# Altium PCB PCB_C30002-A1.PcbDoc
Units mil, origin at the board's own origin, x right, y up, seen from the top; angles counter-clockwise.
Board outline 2417.95 x 1905 mil, 2 copper layers (Top, Bottom), stack 10 mil thick; 53 components, 38 nets, 141 pads, 18 vias.
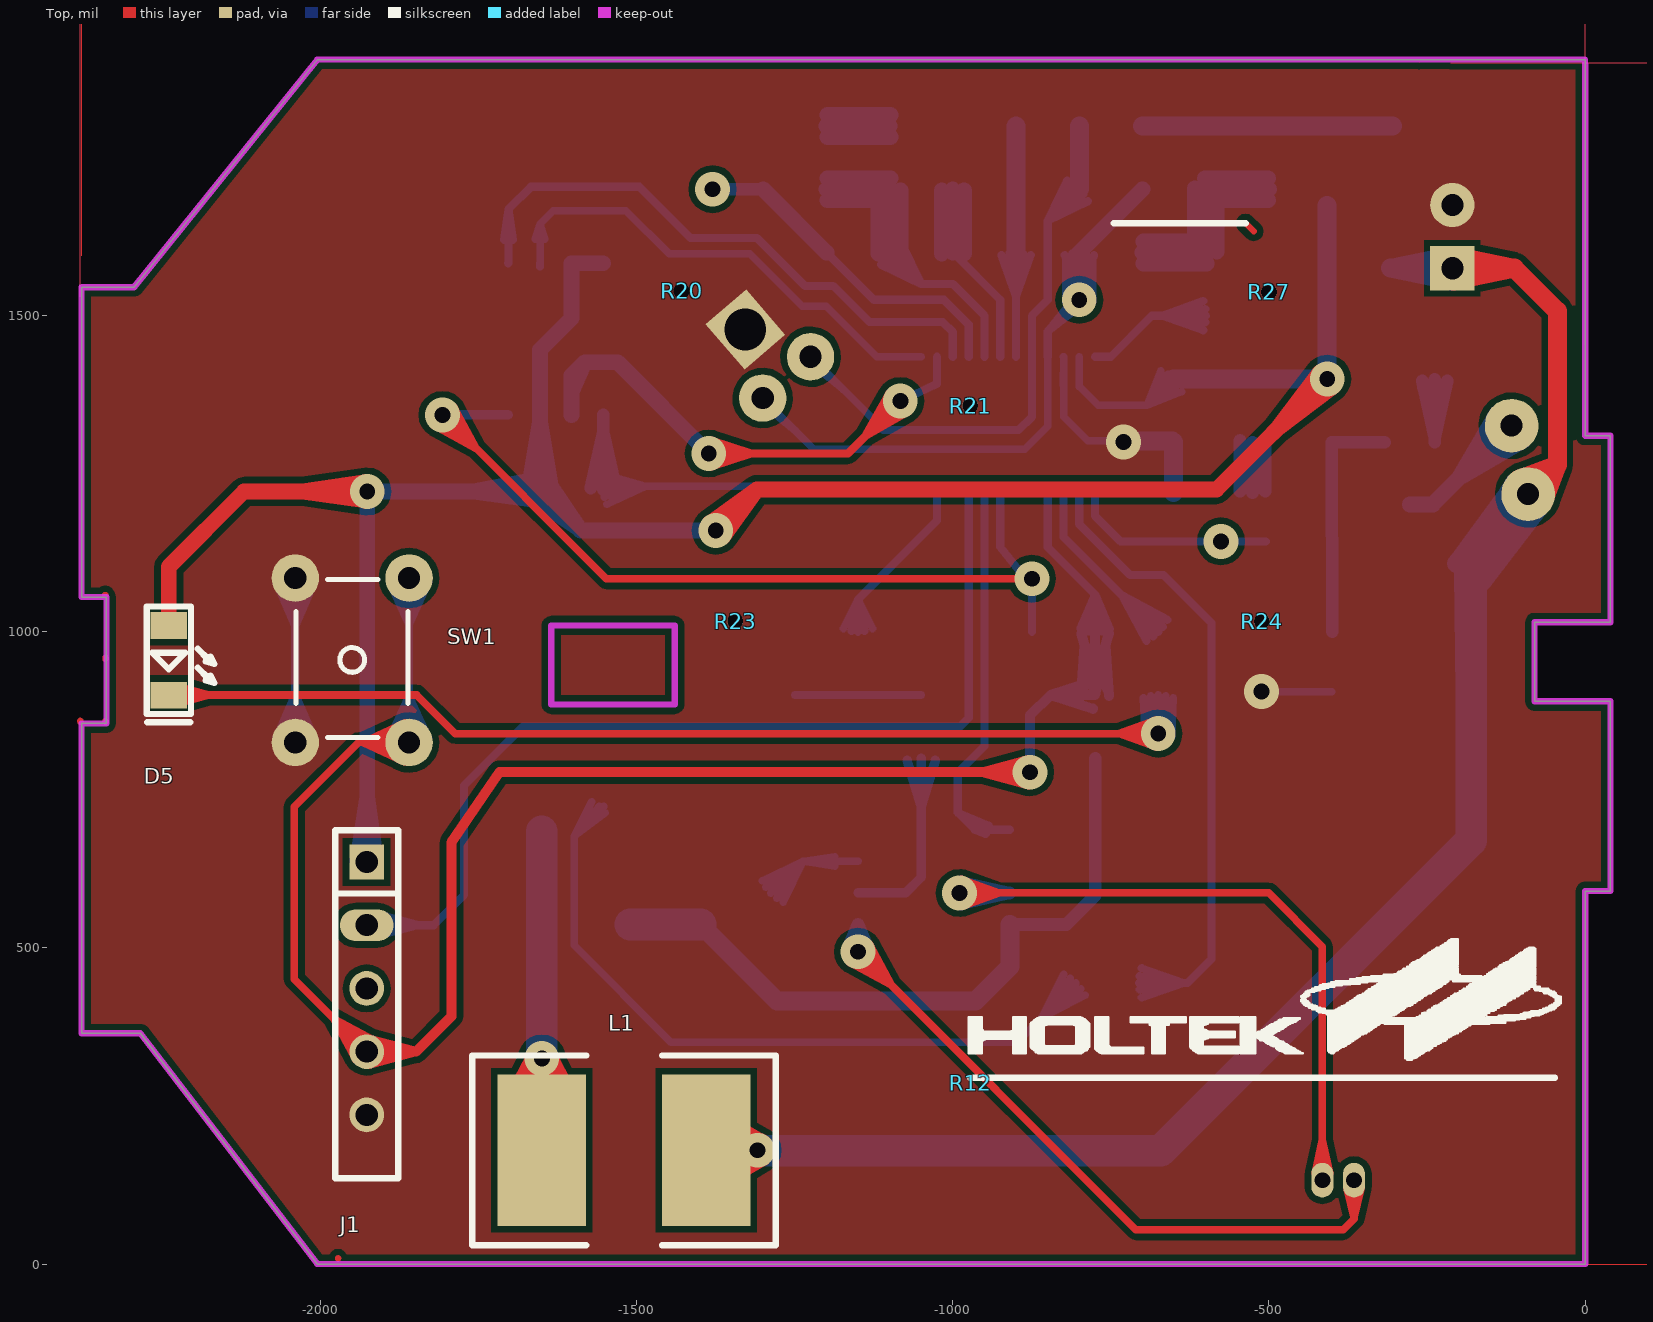
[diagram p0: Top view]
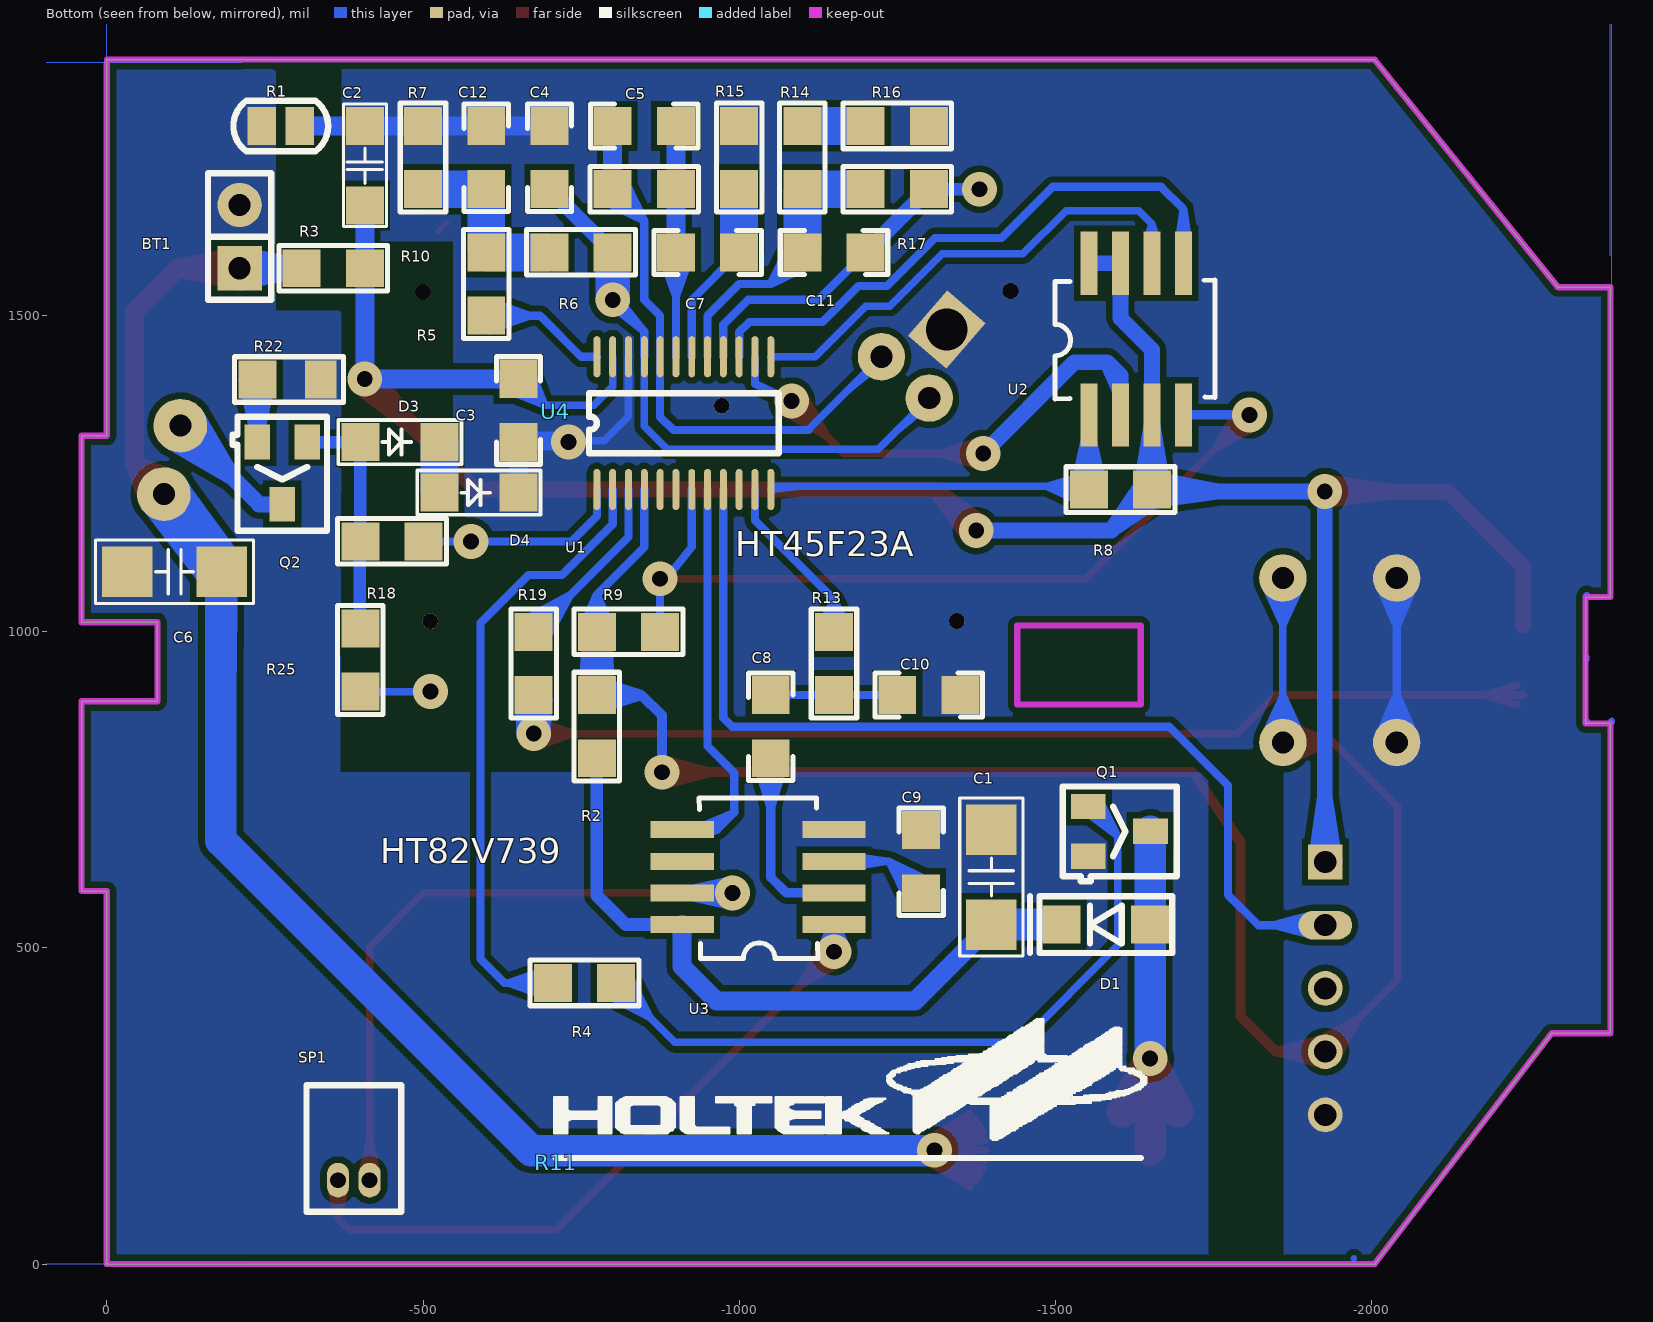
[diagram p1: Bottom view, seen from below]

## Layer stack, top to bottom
Top: signal copper 1
Dielectric: dielectric 8, FR-4, Dk 3.8
Bottom: signal copper 1

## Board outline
0,590 0,0 -2005,0 -2285,365 -2377.95,365 -2377.95,855 -2338.58,855 -2338.58,1055 -2377.95,1055 -2377.95,1545 -2295,1545 -2005,1905 -0.08,1905 0,1895 0,1310 40,1310 40,1015 -80,1015 -80,890 40,890 40,590

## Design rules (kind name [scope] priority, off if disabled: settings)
Clearance [All] p1: gap=10
MinimumSolderMaskSliver [All] p1: minsoldermaskwidth=6
PlaneConnect "Power Plane Connect Style - pads with no thermal" [(Name='J1-3') Or (Name='R20-1') Or (Name='R21-1') Or (Name='R23-1') Or (Name='R24-1') Or (Name='R27-1')] p1: planeconnectstyle=NoConnect reliefexpansion=20 reliefentries=4 reliefconductorwidth=10 reliefairgap=10 // PAD - No Thermal Connect Rule
PlaneConnect [All] p2: planeconnectstyle=Relief reliefexpansion=20 reliefentries=4 reliefconductorwidth=10 reliefairgap=10
PolygonConnect [All] p1: connectstyle=Direct reliefconductorwidth=10 reliefentries=4 polygonreliefangle="90 Angle" airgapwidth=10
RoutingVias [All] p1: holewidth=28 width=50 viastyle="Through Hole" minholewidth=28 minwidth=50 maxholewidth=28 maxwidth=50
SilkToSilkClearance [All] p1: silktosilkclearance=6
SilkscreenOverComponentPads [All] p1: minsilkscreentomaskgap=1
SolderMaskExpansion [All] p1: expansion=4
Width [All] p1: maxlimit=60 minlimit=10 preferedwidth=10
24 further rules are at their usual default settings.

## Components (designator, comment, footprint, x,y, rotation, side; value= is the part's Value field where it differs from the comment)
BT1 "BATAAA" BATAAA -210,1575 r90 bottom
C1 "CAP1206AAA" CAP1206AAA -1399,537 r90 bottom
C2 "CAP1206" CAP1206 -408,1737 r90 bottom
C3 "CAP0805" CAP0805 -651,1300 r90 bottom
C4 "CAP0805" CAP0805 -700,1800 r270 bottom
C5 "CAP0805" CAP0805 -900,1800 r0 bottom
C6 "CAP1206AAA" CAP1206AAA -32,1095 r180 bottom
C7 "CAP0805" CAP0805 -1000,1600 r0 bottom
C8 "CAP0805" CAP0805 -1050,900 r270 bottom
C9 "CAP0805" CAP0805 -1287.8,586.5 r90 bottom
C10 "CAP0805" CAP0805 -1350,900 r0 bottom
C11 "CAP0805" CAP0805 -1200,1600 r0 bottom
C12 "CAP0805" CAP0805 -600,1800 r270 bottom
D1 "DIO1206A" DIO1206A -1650,537 r0 bottom
D3 "DIO0805AA" DIO0805AA -401,1300 r180 bottom
D4 "DIO0805AA" DIO0805AA -526,1220 r180 bottom
D5 "LED\0805_BIN" LED\0805_BIN -2240,955 r270 top
J1 "CON5AAAAA" CON5AAAAA -1927,336 r270 top
L1 "IND-1810AAA" IND-1810AAA -1390,180 r180 top
Q1 "SOT-23S_HOLTEK" SOT-23S_HOLTEK -1552,645 r0 bottom
Q2 "SOT-23S_HOLTEK" SOT-23S_HOLTEK -238,1300 r90 bottom
R1 "JUMPER_SMD-01" JUMPER_SMD-01 -275,1800 r0 bottom
R2 "RES0805" RES0805#1 -775,800 r90 bottom
R3 "RES0805" RES0805#1 -308,1575 r180 bottom
R4 "RES0805" RES0805#1 -705.4,444.6 r180 bottom
R5 "RES0805" RES0805#1 -600,1500 r90 bottom
R6 "RES0805" RES0805#1 -700,1600 r180 bottom
R7 "RES0805" RES0805#1 -500,1800 r270 bottom
R8 "RES0805" RES0805#1 -1653,1225 r0 bottom
R9 "RES0805" RES0805#1 -775,1000 r180 bottom
R10 "RES0805" RES0805#1 -900,1700 r0 bottom
R11 "HOLTEK_LOGO匕AA" HOLTEK_LOGO匕AA -709.7,160 r180 bottom
R12 "HOLTEK_LOGO匕AA" HOLTEK_LOGO匕AA -972.8,286.6 r0 top
R13 "RES0805" RES0805#1 -1150,1000 r270 bottom
R14 "RES0805" RES0805#1 -1100,1800 r270 bottom
R15 "RES0805" RES0805#1 -1000,1800 r270 bottom
R16 "RES0805" RES0805#1 -1200,1800 r180 bottom
R17 "RES0805" RES0805#1 -1200,1700 r180 bottom
R18 "RES0805" RES0805#1 -501,1143 r0 bottom
R19 "RES0805" RES0805#1 -675,1000 r270 bottom
R20 "PUNCHB" PUNCHB -1429,1539.1 r0 top
R21 "PUNCHB" PUNCHB -972.4,1357.5 r0 top
R22 "RES0805" RES0805#2 -338,1399 r0 bottom
R23 "PUNCHAA" PUNCHAA -1344.1,1017 r0 top
R24 "PUNCHB" PUNCHB -511.5,1016.6 r0 top
R25 "RES0805" RES0805#1 -400.8,1005.4 r270 bottom
R27 "PUNCHB" PUNCHB -500,1537.5 r0 top
SP1 "SP1AAA" SP1AAA -415.6,132.7 r0 bottom
SW1 "SW-TS06" SW-TS06 -1950,955 r0 top
U1 "SSOP24A" SSOP24A -775,1225 r90 bottom locked
U2 "SOP8-150" SOP8-150 -1553,1343 r90 bottom
U3 "SOP8-150" SOP8-150 -1150,537 r0 bottom
U4 "SMOKE-5AAAAAAAAAAAAAAAAAA" SMOKE-5AAAAAAAAAAAAAAAAAA -1225,1435 r310.8 bottom locked

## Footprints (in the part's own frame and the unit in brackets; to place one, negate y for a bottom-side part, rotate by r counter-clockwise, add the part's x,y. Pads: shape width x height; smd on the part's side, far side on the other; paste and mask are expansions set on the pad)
BATAAA [mil]
  rect 70x70 / inner round 55 / far side rect 70x70 hole 35: 1(0,0)
  round 70 / inner round 55 / far side round 70 hole 35: 2(100,0)
  silkscreen extent -50,-50 150,50
CAP0805 [mil]
  rect 60x60 smd: 1(0,0) 2(100,0)
  silkscreen extent -35,-35 135,35
CAP1206 [mil]
  rect 60x60 smd: 1(-63,0) 2(63,0)
  silkscreen extent -96,-34 98,34
CAP1206AAA [mil]
  rect 80x80 smd: 1(0,0) 2(150,0)
  silkscreen extent -50,-50 200,50
CON5AAAAA [mil]
  rect 55x55 / inner round 55 / far side rect 55x55 hole 35: 1(-300,0)
  oval 50x85 / inner oval 45x85 / far side oval 45x85 hole 35: 2(-200,0)
  round 55 hole 35: 3(-100,0) 4(0,0) 5(100,0)
  silkscreen extent -350,-50 200,50
DIO0805AA [mil]
  rect 60x60 smd: N(125,0) P(0,0)
  silkscreen extent -35,-35 160,35
DIO1206A [mil]
  rect 60x60 smd: N(140,0) P(0,0)
  silkscreen extent -35,-45 190,45
HOLTEK_LOGO匕AA [mil]
  silkscreen extent -2,8 934,227
IND-1810AAA [mil]
  rect 140x240 smd: 1(0,0) 2(260,0)
  silkscreen extent -110,-150 370,150
JUMPER_SMD-01 [mil]
  rect 45x60 smd: 1(-30,0) 2(30,0)
  silkscreen extent -75,-40 75,40
LED\0805_BIN [mil]
  rect 42x58 smd: A(-55,0) K(55,0)
  silkscreen extent -85,-35 98,72
PUNCHAA [mil]
  round 25 hole 25: 1(0,0)
PUNCHB [mil]
  round 25 hole 25: 1(0,0)
RES0805#1 [mil]
  rect 60x60 smd: 1(0,0) 2(100,0)
  silkscreen extent -36,-36 136,36
RES0805#2 [mil]
  rect 50x60 smd: 1(0,0)
  rect 60x60 smd: 2(100,0)
  silkscreen extent -36,-36 136,36
SMOKE-5AAAAAAAAAAAAAAAAAA [mil]
  round 85 hole 35: 1(906,-717) 2(807,-768)
  round 75 hole 35: 3(0,0) 4(0,100)
  rect 95x80 / inner rect 95x85 / far side rect 95x85 hole 66: 5(-100,50)
SOP8-150 [mil]
  rect 100x27 smd: 1(0,0) 2(0,-50) 3(0,-100) 4(0,-150) 5(240,-150) 6(240,-100) 7(240,-50) 8(240,0)
  silkscreen extent 25,-200 213,54
SOT-23S_HOLTEK [mil]
  rect 55x40 smd: B(0,-78.74) C(-98.43,-39.37) E(0,0)
  silkscreen extent -140,-110 40,39
SP1AAA [mil]
  oval 35x55 hole 25: 1(0,0) 2(50,0)
  silkscreen extent -50,-150 100,50
SSOP24A [mil]
  oval 65x11 smd: 1(0,0) 2(0,-25) 3(0,-50) 4(0,-75) 5(0,-100) 6(0,-125) 7(0,-150) 8(0,-175) 9(0,-200) 10(0,-225) 11(0,-250) 12(0,-275) 13(210,-275) 14(210,-250) 15(210,-225) 16(210,-200) 17(210,-175) 18(210,-150) 19(210,-125) 20(210,-100) 21(210,-75) 22(210,-50) 23(210,-25) 24(210,0)
  silkscreen extent 57,-288 152,12
SW-TS06 [mil]
  round 75 hole 35: 1(90,130) 2(-90,130) 3(90,-130) 4(-90,-130)
  silkscreen extent -89,-122 88,128

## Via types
v1: diameter 55/55 (per signal layer), hole 25, Top to Bottom, 18 vias

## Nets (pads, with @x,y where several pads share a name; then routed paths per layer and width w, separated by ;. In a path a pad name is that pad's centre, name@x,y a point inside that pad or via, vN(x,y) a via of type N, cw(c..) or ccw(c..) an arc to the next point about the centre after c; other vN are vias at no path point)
$$$1: Q2.E R22.2 | length 690.6
  Bottom w20: R22.2@-257.88,1396.78 Q2.E@-238,1309 ; R22.2@-255.52,1386.38 Q2.E@-238,1307.5 ; Q2.E R22.2 Q2.E@-238,1309 ; R22.2@-220.48,1386.38 Q2.E@-238,1307.5 ; R22.2@-218.12,1396.78 Q2.E@-238,1309 ; Q2.E@-238,1307.5 -238,1387.5 Q2.E@-238,1307.5
$$$2: Q1.B R4.2 | length 1704.3
  Bottom w12: Q1.B@-1571.23,731.38 -1597.46,678.28 ; Q1.B@-1559.5,723.74 -1597.46,678.28 ; Q1.B -1599,676.74 -1599,504 -1445.9,350.9 -898,350.9 -805.4,443.5 R4.2 -860.13,388.77 ; Q1.B@-1549.89,713.56 -1597.46,678.28 ; R4.2@-824.91,458.57 -860.13,388.77 ; R4.2@-814.59,452.32 -860.13,388.77 ; R4.2@-797.5,435.57 -860.13,388.77 ; R4.2@-791.04,425.37 -860.13,388.77
$$$3: D3.N D4.P | length 720
  Bottom w20: D3.N@-545.84,1297.5 D4.P ; D3.N@-545.84,1302.5 D4.P@-545.84,1222.5 ; D3.N@-544.6,1292.66 D4.P@-506.16,1222.5 ; D3.N@-507.4,1292.66 D4.P@-545.84,1222.5 ; D3.N@-506.16,1297.5 D4.P ; D3.N@-506.16,1302.5 D4.P@-506.16,1222.5 ; D4.P@-545.84,1222.5 D3.N ; D4.P D3.N ; D3.N D4.P@-506.16,1222.5
GND: BT1.2 C1.2 C2.2 C3.1 C4.1 C6.1 C9.2 C10.1 C12.1 D4.N J1.5 Q1.E R1.1 R1.2 R7.1 R15.1 R16.2 R20.1 R21.1 R22.1 R23.1 R24.1 R25.2 R27.1 SW1.2 SW1.4 U1.22 U3.4 U4.5 | length 1783.2
  Bottom w12: U1.22@-825,1409 -824.7,1366.5 ; U1.22 -824.7,1434.7 -824.7,1340 -786.7,1302 v1@-719,1302 ; v1(-511.9,905.4) R25.2
  Bottom w13: SW1.4@-2070.36,831.28 -2040,901.5 ; SW1.2@-2070.36,1078.72 -2040,1008.5 ; SW1.4@-2057.88,827.12 -2040,901.5 ; SW1.2@-2057.88,1082.88 -2040,1008.5 ; SW1.4 SW1.2 ; SW1.4@-2022.12,827.12 -2040,901.5 ; SW1.2@-2022.12,1082.88 -2040,1008.5 ; SW1.4@-2009.64,831.28 -2040,901.5 ; SW1.2@-2009.64,1078.72 -2040,1008.5
  Bottom w30: v1@-719,1302 C3.1@-653,1302 ; C4.1 C2.2 R1.1 ; D4.N C3.1
  other v1: -730,1300
GND_F: 
N58961: C7.1 R15.2 U1.18 | length 1141.6
  Bottom w13: C7.1 -925,1525 U1.18 ; U1.18@-925,1461 -925,1506.5
  Bottom w25: C7.1@-1017.43,1598.47 R15.2@-1017.43,1698.47 ; C7.1@-1017.43,1601.53 R15.2 ; C7.1@-1016.9,1604.55 R15.2@-982.57,1698.47 ; C7.1@-983.1,1604.55 R15.2@-1017.43,1698.47 ; C7.1@-982.57,1598.47 R15.2@-982.57,1698.47 ; C7.1@-982.57,1601.53 R15.2 ; R15.2@-1017.43,1698.47 C7.1 ; C7.1 R15.2@-982.57,1698.47 ; C7.1 R15.2
N59111: U1.8 U3.5 | length 938.4
  Bottom w13: U3.5@-950.46,681.23 -992.1,714 ; -950,1153.5 U1.8@-950,1199 ; U1.8 -950,819.3 -992.1,777.2 -992.1,714 ; U3.5@-943.34,693.25 -992.1,714 ; U3.5 -910.1,687.1 -965.2,687.1 ; -992.1,714 U3.5@-946.5,687 ; -992.1,714 -965.2,687.1 ; -965.2,687.1 U3.5@-946.5,687 ; -965.2,687.1 -947.77,693.88 -965.2,687.1 ; -965.2,687.1 -947.85,680.13 -965.2,687.1 ; -965.2,687.1 U3.5@-946.5,687
N59151: R14.1 R16.1 | length 900
  Bottom w25: R14.1@-1104.55,1783.1 R16.1@-1198.47,1817.43 ; R14.1@-1104.55,1816.9 R16.1@-1198.47,1782.57 ; R14.1@-1101.53,1782.57 R16.1 ; R14.1@-1101.53,1817.43 R16.1 ; R14.1@-1098.47,1782.57 R16.1@-1198.47,1782.57 ; R14.1@-1098.47,1817.43 R16.1@-1198.47,1817.43 ; R16.1 R14.1 ; R16.1@-1198.47,1782.57 R14.1 ; R16.1@-1198.47,1817.43 R14.1
N59187: C5.1 C7.2 R10.1 U1.19 | length 786.5
  Bottom w13: C7.2@-923.16,1596 -900,1531 ; C7.2@-910.47,1599.2 -900,1531 ; U1.19 C7.2 ; U1.19@-900,1461 -900,1506.5 ; C7.2@-889.53,1599.2 -900,1531 ; C7.2@-876.84,1596 -900,1531
  Bottom w30: C5.1 R10.1 ; R10.1 C7.2 R10.1
N59191: R5.1 U1.24 | length 477.9
  Bottom w13: U1.24 -750,1435 -685,1500 R5.1 ; R5.1@-604,1476.84 -669,1500 ; R5.1@-604,1523.16 -669,1500 ; R5.1@-600.8,1489.53 -669,1500 ; R5.1@-600.8,1510.47 -669,1500
N59345: R8.2 U1.12 U2.1 | length 1590.3
  Bottom w12: R8.2 -1486.63,1230 ; R8.2@-1553,1230 -1055,1230 U1.12 -1096.16,1230 ; R8.2@-1552.82,1237 -1486.63,1230 ; R8.2@-1551.02,1213.16 -1486.63,1230 ; R8.2@-1550.46,1248.87 -1486.63,1230 ; R8.2@-1546.91,1201.79 -1486.63,1230
  Bottom w20: R8.2@-1572.88,1227.22 U2.1@-1553,1315 ; R8.2@-1572.85,1227.45 U2.1@-1553,1306.5 ; R8.2@-1553,1233 U2.1@-1553,1306.5 ; U2.1 -1553,1230 R8.2 ; R8.2@-1533.15,1227.45 U2.1@-1553,1306.5 ; R8.2@-1533.12,1227.22 U2.1@-1553,1315 ; R8.2 U2.1@-1553,1306.5 ; R8.2 U2.1@-1553,1315
N59413: R18.1 U1.1 | length 344.6
  Bottom w13: U1.1@-775,1199 -775,1183 ; U1.1 -775,1183 ; R18.1@-505,1143 -735,1143 -775,1183
  other v1: -576,1143
N59565: D1.P L1.2 Q1.C | length 936.9
  Top w50: L1.2@-1693.72,240.66 v1(-1650,325) ; L1.2 v1(-1650,325) ; L1.2@-1650,230 v1(-1650,325) ; L1.2@-1606.28,240.66 v1(-1650,325)
  Bottom w50: v1(-1650,325) D1.P ; D1.P Q1.C -1650,683.94 D1.P
N59677: C9.1 U3.3 | length 593.5
  Bottom w12: C9.1@-1301.68,606.08 -1237.2,637.1 ; C9.1@-1295.54,595.67 -1237.2,637.1 ; C9.1 -1237.2,637.1 ; C9.1@-1278.63,578.76 -1237.2,637.1 ; C9.1@-1268.22,572.62 -1237.2,637.1 ; U3.3@-1187.08,629.52 -1236,637.1 ; U3.3@-1187.05,644.48 -1236,637.1 ; U3.3@-1186.5,637 -1236,637.1 ; U3.3 -1150.1,637.1 -1237.2,637.1
N59689: R9.2 U1.7 U2.4 | length 1734.1
  Top w12: v1@-1819.86,1325.77 -1754.04,1290.04 ; v1@-1813.28,1335.87 -1754.04,1290.04 ; v1(-1807,1343) -1548,1084 v1(-875,1084) ; v1@-1799.87,1349.28 -1754.04,1290.04 ; v1@-1789.77,1355.86 -1754.04,1290.04
  Bottom w13: -925,1153.5 U1.7@-925,1199 ; U1.7 -925,1134 v1@-880.97,1078.67 ; R9.2 v1(-875,1084)
  Bottom w15: v1(-1807,1343) U2.4
N59731: C8.2 U3.2 | length 487.3
  Bottom w15: U3.2 -1074.7,587 ; U3.2@-1113.5,587 -1074.7,587 ; C8.2@-1072.25,796.62 -1050,725 C8.2@-1027.75,796.62 ; C8.2 -1050,611.7 -1074.7,587
N59775: D5.K R19.2 | length 3540.3
  Top w12: D5.K -1848,900 -1787,839 v1(-675,839) ; D5.K@-2232,900 -2175,900 ; D5.K@-2230.03,885.13 -2175,900 ; D5.K@-2230.03,914.87 -2175,900 ; v1@-678.64,817.81 -738.5,839 ; v1@-678.64,860.19 -738.5,839 ; v1@-675.71,829.53 -738.5,839 ; v1@-675.71,848.47 -738.5,839
  Bottom w12: v1@-696.5,838.57 R19.2@-686.94,898.82 ; v1@-696.16,842.79 R19.2 ; v1@-695.99,834.33 R19.2@-698.53,895.28 ; v1@-695.01,846.86 R19.2@-663.06,898.82 ; v1@-693.06,850.66 R19.2@-651.47,895.28 ; v1@-684.43,837.87 R19.2@-686.94,898.82 ; v1@-684.47,839.74 R19.2 ; v1@-684.14,841.58 R19.2@-663.06,898.82 ; v1@-684.02,836.03 R19.2@-698.53,895.28 ; v1@-683.45,843.34 R19.2@-651.47,895.28 ; v1@-666.55,843.34 R19.2@-698.53,895.28 ; v1@-665.98,836.03 R19.2@-651.47,895.28 ; v1@-665.86,841.58 R19.2@-686.94,898.82 ; v1@-665.57,837.87 R19.2@-663.06,898.82 ; v1@-665.53,839.74 R19.2 ; v1@-656.94,850.66 R19.2@-698.53,895.28 ; v1@-654.99,846.86 R19.2@-686.94,898.82 ; v1@-654.01,834.33 R19.2@-651.47,895.28 ; v1@-653.84,842.79 R19.2 ; v1@-653.5,838.57 R19.2@-663.06,898.82 ; R19.2@-698.53,895.28 v1(-675,839) ; R19.2@-686.94,898.82 v1(-675,839) ; v1(-675,839) R19.2@-663.06,898.82 ; v1(-675,839) R19.2@-651.47,895.28 ; v1(-675,839) R19.2
N59783: C11.2 R14.2 R17.1 U1.17 | length 3078.3
  Bottom w13: C11.2@-1113.62,1580.85 -1050,1550 ; C11.2@-1106.85,1592.04 -1050,1550 ; C11.2 -1050,1550 ; C11.2@-1092.04,1606.85 -1050,1550 ; C11.2@-1080.85,1613.62 -1050,1550 ; U1.17 -950,1500 ; U1.17@-950,1461 -950,1500 ; -1050,1550 -1000,1550 -950,1500
  Bottom w25: C11.2@-1117.43,1598.47 R14.2@-1117.43,1698.47 ; C11.2@-1116.9,1604.55 R14.2@-1082.57,1698.47 ; R14.2@-1104.55,1683.1 R17.1@-1198.47,1717.43 ; R14.2@-1104.55,1716.9 R17.1@-1198.47,1682.57 ; R14.2@-1101.53,1682.57 R17.1 ; R14.2@-1101.53,1717.43 R17.1 ; R14.2@-1098.47,1682.57 R17.1@-1198.47,1682.57 ; R14.2@-1098.47,1717.43 R17.1@-1198.47,1717.43 ; C11.2@-1083.1,1604.55 R14.2@-1117.43,1698.47 ; C11.2@-1082.57,1598.47 R14.2@-1082.57,1698.47 ; R17.1 R14.2 ; R17.1 R14.2 ; R17.1@-1198.47,1682.57 R14.2 ; R17.1@-1198.47,1682.57 R14.2 ; R17.1@-1198.47,1717.43 R14.2 ; R17.1@-1198.47,1717.43 R14.2 ; R14.2@-1117.43,1698.47 C11.2 ; R14.2@-1117.43,1698.47 C11.2 ; C11.2 R14.2 ; C11.2 R14.2@-1082.57,1698.47 ; C11.2 R14.2 ; R14.2 -1082.57,1601.53 R14.2 ; R14.2 -1117.43,1601.53 R14.2
N59905: Q2.C U4.2 | length 565.4
  Bottom w25: Q2.C -240.75,1201.57 U4.2 -199.48,1242.84 ; U4.2@-140.06,1344.34 -199.48,1242.84 ; U4.2@-97.98,1302.26 -199.48,1242.84
N59951: R19.1 U1.3 | length 739.8
  Bottom w13: -825,1153.5 U1.3@-825,1199 ; U1.3 -825,1150 R19.1 -732.58,1057.58 ; R19.1@-693.84,985.95 -732.58,1057.58 ; R19.1@-682.89,993.07 -732.58,1057.58 ; R19.1@-668.07,1007.89 -732.58,1057.58 ; R19.1@-660.95,1018.84 -732.58,1057.58
N59955: C8.1 C10.2 R13.2 | length 200
  Bottom w12: C10.2 C8.1
N60019: U1.13 U2.6 | length 900.3
  Bottom w12: U2.6@-1660.41,1620.65 -1652.8,1645.3 ; U2.6 -1653,1577.5 -1652.8,1577.7 -1652.8,1645.3 ; U2.6@-1653,1619.5 -1652.8,1645.3 ; U2.6@-1645.57,1620.53 -1652.8,1645.3 ; -1092.5,1435 U1.13 -1120,1435 -1200,1515 -1238.3,1515 -1320.9,1597.6 -1448.7,1597.6 -1517.1,1666 -1632.1,1666 -1652.8,1645.3
N60099: SP1.1 U3.7 | length 1759.1
  Top w12: v1(-989.3,587) -500.4,587 -415.6,502.2 SP1.1 ; v1@-988.59,577.53 -925.8,587 ; v1@-988.59,596.47 -925.8,587 ; v1@-985.66,565.81 -925.8,587 ; v1@-985.66,608.19 -925.8,587 ; SP1.1@-427.03,143.94 -415.6,196.2 ; SP1.1@-415.6,142.7 -415.6,196.2 ; SP1.1@-404.17,143.94 -415.6,196.2
  Bottom w20: v1@-987.37,569.61 U3.7 ; v1@-987.37,604.39 U3.7 ; v1@-985.72,569.87 U3.7@-946.5,587 ; v1@-985.72,604.13 U3.7@-946.5,587 ; U3.7@-946.5,587 v1(-989.3,587) U3.7
N60269: U1.14 U2.2 | length 1489.8
  Top w13: v1(-1386,1282) -1166,1282 v1(-1083,1365) ; v1@-1385.52,1274.01 -1319.5,1282 ; v1@-1385.52,1289.99 -1319.5,1282 ; v1@-1382.68,1261.26 -1319.5,1282 ; v1@-1382.68,1302.74 -1319.5,1282 ; v1@-1099.72,1377.71 -1138.08,1309.92 ; v1@-1088.94,1370.36 -1138.08,1309.92 ; v1@-1077.64,1359.06 -1138.08,1309.92 ; v1@-1070.29,1348.28 -1138.08,1309.92
  Bottom w13: v1(-1083,1365) -1025,1392 ; U1.14@-1025,1409 -1025,1392 ; U1.14 -1025,1392
  Bottom w25: U2.2 -1603,1405.5 ; v1(-1386,1282) -1530.2,1426.2 -1582.3,1426.2 ; U2.2@-1603,1379.5 -1603,1405.5 ; U2.2@-1603,1379.5 -1603,1405.5 ; U2.2@-1603,1379.5 -1582.3,1426.2 ; -1603,1405.5 -1582.3,1426.2
N60313: SP1.2 U3.1 | length 1616
  Top w12: v1@-1162.86,476.77 -1097.04,441.04 ; v1@-1156.28,486.87 -1097.04,441.04 ; v1(-1150,494) -710.4,54.4 -382.9,54.4 -365.5,71.8 ; v1@-1142.87,500.28 -1097.04,441.04 ; v1@-1132.77,506.86 -1097.04,441.04 ; SP1.2@-377.02,121.38 -365.5,71.8 ; SP1.2@-365.6,122.7 -365.5,71.8 ; SP1.2 -365.5,132.6 -365.5,71.8 ; SP1.2@-354.17,121.42 -365.5,71.8
  Bottom w20: v1@-1167.13,497.56 U3.1 ; v1(-1150,494) U3.1 ; v1@-1132.87,497.56 U3.1
N60321: R13.1 U1.11 | length 503.8
  Bottom w13: R13.1@-1172.87,1005.41 -1150,1051 ; R13.1@-1160.44,1001.08 -1150,1051 ; R13.1 -1150,1051 ; R13.1@-1139.56,1001.08 -1150,1051 ; R13.1@-1127.13,1005.41 -1150,1051 ; U1.11@-1025,1199 -1025,1176 ; U1.11 -1025,1176 ; -1150,1051 -1025,1176
N60475: U1.15 U2.5 | length 1109.7
  Bottom w13: U2.5@-1709.98,1620.04 -1702.7,1668.4 ; U2.5 -1702.7,1583.3 -1702.7,1668.4 ; U2.5@-1703,1619.5 -1702.7,1668.4 ; U2.5@-1696.01,1619.96 -1702.7,1668.4 ; U1.15 -1000,1474 ; -1702.7,1668.4 -1667.4,1703.7 -1495.7,1703.7 -1415,1623 -1309.8,1623 -1233.8,1547 -1189,1547 -1132,1490 -1016,1490 -1000,1474 ; -1000,1474 -1000,1461 -1000,1474
N64972: C11.1 R17.2 U1.16 | length 569.6
  Bottom w13: C11.1 -1125,1525 -1014,1525 -975,1486 ; U1.16 -975,1486 ; U1.16@-975,1461 -975,1486
  Bottom w20: v1(-1380,1700) R17.2
  Bottom w25: R17.2 C11.1
N66814: R4.1 U1.2 | length 1295.3
  Bottom w13: U1.2@-800,1199 -800,1170 ; U1.2 -800,1170 ; R4.1 -628.9,444.6 -590.9,482.6 -590.9,1013.9 -667,1090 -720,1090 -800,1170 ; R4.1@-704.6,434.13 -636.4,444.6 ; R4.1@-704.6,455.07 -636.4,444.6 ; R4.1@-701.4,421.44 -636.4,444.6 ; R4.1@-701.4,467.76 -636.4,444.6
N67509: C12.2 R5.2 R6.1 R7.2 | length 3000
  Bottom w25: C12.2@-617.43,1698.47 R5.2 ; C12.2@-617.43,1701.53 R5.2@-617.43,1601.53 ; C12.2@-616.9,1695.45 R5.2@-582.57,1601.53 ; R5.2@-604.55,1583.1 R6.1@-698.47,1617.43 ; R5.2@-604.55,1616.9 R6.1@-698.47,1582.57 ; R5.2@-601.53,1582.57 R6.1 ; R5.2@-601.53,1617.43 R6.1 ; C12.2@-601.53,1682.57 R7.2@-501.53,1682.57 ; C12.2@-601.53,1717.43 R7.2@-501.53,1717.43 ; R5.2@-598.47,1582.57 R6.1@-698.47,1582.57 ; R5.2@-598.47,1617.43 R6.1@-698.47,1617.43 ; C12.2@-598.47,1682.57 R7.2 ; C12.2@-598.47,1717.43 R7.2 ; C12.2@-595.45,1683.1 R7.2@-501.53,1717.43 ; C12.2@-595.45,1716.9 R7.2@-501.53,1682.57 ; C12.2@-583.1,1695.45 R5.2@-617.43,1601.53 ; C12.2@-582.57,1698.47 R5.2 ; C12.2@-582.57,1701.53 R5.2@-582.57,1601.53 ; R6.1 R5.2 ; R6.1 R5.2 ; R6.1@-698.47,1582.57 R5.2 ; R6.1@-698.47,1582.57 R5.2 ; R6.1@-698.47,1617.43 R5.2 ; R6.1@-698.47,1617.43 R5.2 ; R5.2@-617.43,1601.53 C12.2 ; R5.2 C12.2 ; C12.2 R5.2@-582.57,1601.53 ; C12.2 R7.2@-501.53,1717.43 ; C12.2 R7.2@-501.53,1682.57 ; C12.2 R7.2
N71817: D3.P Q2.B R18.2 R25.1 | length 384.3
  Bottom w20: R25.1@-400,1000 D3.P Q2.B
PA0: J1.4 R2.2 R9.1 SW1.1 SW1.3 U1.4 | length 6483.7
  Top w12: J1.4@-1944.23,323.14 -1979.96,388.96 ; J1.4@-1934.13,329.72 -1979.96,388.96 ; J1.4@-1920.72,343.13 -1979.96,388.96 ; J1.4@-1914.14,353.23 -1979.96,388.96 ; SW1.3@-1866.75,794.23 -1933.5,825 ; SW1.3@-1866.75,855.77 -1933.5,825 ; SW1.3@-1862.59,805.67 -1933.5,825 ; SW1.3@-1862.59,844.33 -1933.5,825 ; SW1.3@-1860.38,817.51 -1933.5,825 ; SW1.3@-1860.38,832.49 -1933.5,825 ; -1979.96,388.96 J1.4 -2041.6,450.6 -2041.6,723.3 -1939.9,825 SW1.3 -1933.5,825
  Top w16: J1.4 -1849,336 -1793,392 -1793,667 -1717,778 v1(-878,778) ; J1.4@-1924.48,316.66 -1851.5,336 J1.4@-1924.48,355.34 ; v1@-880.52,758.66 -953.5,778 v1@-880.52,797.34
  Bottom w12: SW1.3@-1890.77,831.75 -1860,898.5 ; SW1.1@-1890.77,1078.25 -1860,1011.5 ; SW1.3@-1879.33,827.59 -1860,898.5 ; SW1.1@-1879.33,1082.41 -1860,1011.5 ; SW1.3@-1867.49,825.38 -1860,898.5 ; SW1.1@-1867.49,1084.62 -1860,1011.5 ; SW1.3 SW1.1 ; SW1.3@-1852.51,825.38 -1860,898.5 ; SW1.1@-1852.51,1084.62 -1860,1011.5 ; SW1.3@-1840.67,827.59 -1860,898.5 ; SW1.1@-1840.67,1082.41 -1860,1011.5 ; SW1.3@-1829.23,831.75 -1860,898.5 ; SW1.1@-1829.23,1078.25 -1860,1011.5
  Bottom w13: -850,1153.5 U1.4@-850,1199 ; U1.4 -850,1134 -775,1059 ; R9.1@-798.03,1004.68 -775,1059 ; R9.1@-785.46,1000.93 -775,1059 ; R9.1 -775,1059 ; R9.1@-764.54,1000.93 -775,1059 ; R9.1@-751.97,1004.68 -775,1059
  Bottom w16: v1(-878,778) -878,868 -845,900 ; R2.2@-796.95,898.51 R9.1@-791.32,978.14 ; R9.1@-796.78,996.9 R2.2@-775,922 ; R2.2@-795.71,907.42 R9.1@-758.68,978.14 ; R2.2@-778.46,878.27 -845,900 ; R2.2@-778.46,921.73 -845,900 ; R2.2@-754.29,907.42 R9.1@-791.32,978.14 ; R9.1@-753.22,996.9 R2.2@-775,922 ; R2.2@-753.05,898.51 R9.1@-758.68,978.14 ; -845,900 R2.2 ; R9.1@-791.32,978.14 R2.2 ; R2.2 R9.1@-758.68,978.14 ; R2.2 R9.1@-775,978 ; R2.2 R9.1 R2.2@-775,922 ; R9.1@-775,978 -753.22,903.1 R9.1@-775,978 ; R9.1@-775,978 -796.78,903.1 R9.1@-775,978
RES: J1.2 U1.9 | length 1780.2
  Bottom w13: J1.2 -1821,536 -1773,584 -1773,757 -1680,850 -989,850 -975,864 U1.9 ; J1.2@-1907,536 -1845.5,536 ; J1.2@-1904.92,520.14 -1845.5,536 ; J1.2@-1904.92,551.86 -1845.5,536 ; -975,1153.5 U1.9@-975,1199
V+5: C1.1 D1.N R2.1 U3.8 | length 1229.7
  Bottom w20: U3.8 -820.6,537 ; U3.8@-873.5,537 -820.6,537 ; R2.1 -775,582.6 -820.6,537
  Bottom w30: C1.1 -1278.4,416.4 -964,416.4 -909.8,470.6 ; -909.8,470.6 U3.8 -909.8,536.8 -909.8,470.6
  Bottom w50: D1.N C1.1
VBAT: BT1.1 C6.2 L1.1 R3.1 U4.1 | length 9294.9
  Top w12: L1.1 v1(-1309,180) ; L1.1@-1388.42,164.08 v1(-1309,180) ; L1.1@-1388.42,195.92 v1(-1309,180) ; L1.1@-1385.16,152.42 v1(-1309,180) ; L1.1@-1385.16,207.58 v1(-1309,180) ; L1.1@-1380.12,141.24 v1(-1309,180) ; L1.1@-1380.12,218.76 v1(-1309,180) ; L1.1@-1373.31,130.75 v1(-1309,180) ; L1.1@-1373.31,229.25 v1(-1309,180) ; L1.1@-1364.72,121.21 v1(-1309,180) ; L1.1@-1364.72,238.79 v1(-1309,180) ; L1.1@-1326.59,167.64 L1.1@-1359.82,233.63 ; L1.1@-1326.59,192.36 L1.1@-1359.82,126.37 ; L1.1@-1324.52,165.12 L1.1@-1365.08,222.95 ; L1.1@-1324.52,194.88 L1.1@-1365.08,137.05 ; L1.1@-1322.17,163.01 L1.1@-1368.11,212.21 ; L1.1@-1322.17,196.99 L1.1@-1368.11,147.79 ; v1@-1319.55,161.27 L1.1@-1370.35,202.22 ; v1@-1319.55,198.73 L1.1@-1370.35,157.78 ; v1@-1316.7,159.93 L1.1@-1371.8,192.59 ; v1@-1316.7,200.07 L1.1@-1371.8,167.41 ; v1@-1316.3,173.92 L1.1@-1359.82,233.63 ; v1@-1316.3,186.08 L1.1@-1359.82,126.37 ; v1@-1315.27,172.86 L1.1@-1365.08,222.95 ; v1@-1315.27,187.14 L1.1@-1365.08,137.05 ; v1@-1314.12,172 L1.1@-1368.11,212.21 ; v1@-1314.12,188 L1.1@-1368.11,147.79 ; v1@-1312.88,171.33 L1.1@-1370.35,202.22 ; v1@-1312.88,188.67 L1.1@-1370.35,157.78 ; v1@-1312.64,158.81 L1.1@-1372.5,180 ; v1@-1312.64,201.19 L1.1@-1372.5,180 ; v1@-1311.55,170.85 L1.1@-1371.8,192.59 ; v1@-1311.55,189.15 L1.1@-1371.8,167.41 ; v1@-1309.71,170.53 L1.1@-1372.5,180 ; v1@-1309.71,189.47 L1.1@-1372.5,180 ; v1@-1308.37,158.51 L1.1@-1371.8,167.41 ; v1@-1308.37,201.49 L1.1@-1371.8,192.59 ; v1@-1307.83,170.57 L1.1@-1371.8,167.41 ; v1@-1307.83,189.43 L1.1@-1371.8,192.59 ; v1@-1306.42,170.86 L1.1@-1370.35,157.78 ; v1@-1306.42,189.14 L1.1@-1370.35,202.22 ; v1@-1305.11,158.85 L1.1@-1370.35,157.78 ; v1@-1305.11,201.15 L1.1@-1370.35,202.22 ; v1@-1305.05,171.36 L1.1@-1368.11,147.79 ; v1@-1305.05,188.64 L1.1@-1368.11,212.21 ; v1@-1303.74,172.09 L1.1@-1365.08,137.05 ; v1@-1303.74,187.91 L1.1@-1365.08,222.95 ; v1@-1302.54,173.04 L1.1@-1359.82,126.37 ; v1@-1302.54,186.96 L1.1@-1359.82,233.63 ; v1@-1301.86,159.72 L1.1@-1368.11,147.79 ; v1@-1301.86,200.28 L1.1@-1368.11,212.21 ; v1@-1298.68,161.14 L1.1@-1365.08,137.05 ; v1@-1298.68,198.86 L1.1@-1365.08,222.95 ; v1@-1295.71,163.1 L1.1@-1359.82,126.37 ; v1@-1295.71,196.9 L1.1@-1359.82,233.63
  Top w30: BT1.1 -112,1575 ; BT1.1@-207.96,1555.1 -112,1575 ; BT1.1@-207.96,1594.9 -112,1575 ; U4.1@-105.14,1240.85 -44,1263.96 ; U4.1@-67.12,1202.82 -44,1263.96 ; -112,1575 -44,1507 -44,1263.96 ; -44,1263.96 U4.1 -44,1263.96
  Bottom w12: v1@-1309,179 v1(-1309,180)
  Bottom w30: BT1.1@-212.04,1555.1 R3.1 ; BT1.1@-212.04,1594.9 R3.1 ; BT1.1 R3.1 ; C6.2@-203.42,1107.9 U4.1@-121.24,1220.1 ; C6.2@-197.42,1114.68 U4.1@-72.94,1196.35 ; C6.2@-163.5,1078.18 U4.1@-72.94,1196.35 ; C6.2@-158.62,1086.14 U4.1@-121.24,1220.1 ; U4.1@-111.62,1235.02 C6.2@-182,1125.96 ; C6.2 U4.1@-96.27,1211.7 ; C6.2 U4.1@-72.94,1196.35 ; C6.2 U4.1@-96.27,1211.7 ; C6.2 U4.1@-121.24,1220.1 ; C6.2 C6.2@-182,1125.96 ; C6.2@-182,1125.96 U4.1 C6.2@-182,1125.96 ; C6.2@-182,1125.96 U4.1@-72.94,1196.35 ; U4.1@-96.27,1211.7 -160.65,1081.99 U4.1@-96.27,1211.7 ; U4.1@-96.27,1211.7 -200.79,1111.49 U4.1@-96.27,1211.7
  Bottom w50: v1@-1309,179 -671,179 -180,670 -180,1093 C6.2 -180,904.96
VDD: C2.1 C3.2 D5.A J1.1 R3.2 R8.1 U1.23 U2.3 U2.7 U2.8 | length 6286.1
  Top w25: D5.A -2240,1103 -2121,1222 v1(-1926,1222) ; v1@-1927.1,1207.04 -2028.5,1222 v1@-1927.1,1236.96 ; v1@-1384.71,1171.44 -1310,1225 ; v1(-1375,1160) -1310,1225 ; v1@-1363.56,1150.29 -1310,1225 ; v1@-419.28,1409.89 -488.53,1319.47 v1@-398.11,1388.72 ; v1(-408,1400) -583,1225 -1310,1225
  Bottom w12: J1.1 J1.1@-1926,637 ; U1.23@-800,1409 -800,1388 ; U1.23 -800,1388 ; C3.2@-671.07,1413.16 -692.89,1358 ; C3.2@-660.31,1407.57 -692.89,1358 ; C3.2 -692.89,1358 ; C3.2@-650.89,1400 -692.89,1358 ; C3.2@-643.4,1390.71 -692.89,1358 ; C3.2@-637.79,1379.96 -692.89,1358 ; -800,1388 -770,1358 -692.89,1358
  Bottom w25: J1.1@-1941.95,637.24 -1926,738.52 ; J1.1 -1926,738.52 ; J1.1@-1926,637 v1(-1926,1222) R8.1@-1656,1222 ; J1.1@-1912.03,636.95 -1926,738.52 ; R8.1@-1670.44,1226.46 -1653,1330 R8.1@-1635.56,1226.46 ; R8.1@-1670.4,1226.88 U2.3@-1653,1306.5 ; R8.1@-1664.12,1211.49 -1589,1161 ; R8.1@-1654.95,1242.39 -1758.13,1222 ; R8.1@-1653.96,1207.53 -1758.13,1222 ; U2.3@-1653,1379.5 -1653,1446 ; R8.1@-1639.49,1236.12 -1589,1161 ; R8.1@-1635.6,1226.88 U2.3@-1653,1306.5 ; U2.7@-1603,1546.5 -1603,1496 ; U2.8 U2.7 -1603,1496 ; v1(-1375,1160) -1589,1160 -1589,1161 ; -1758.13,1222 R8.1 ; R8.1 U2.3@-1653,1306.5 ; R8.1 U2.3 -1653,1446 ; R8.1 -1589,1161 ; -1653,1446 -1603,1496
  Bottom w30: -531,1400 C3.2 -650.89,1400 v1(-408,1400) R3.2 C2.1
X00034: C4.2 R6.2 U1.21 U4.4 | length 3168
  Bottom w12: U4.4@-1305.72,1364.09 -1248.65,1317.61 ; U4.4 -1220.04,1289 -886,1289 -850,1325 U1.21 ; -850,1366.5 U1.21@-850,1409
  Bottom w13: U1.21 -850,1475 ; U1.21@-850,1461 -850,1475 ; R6.2@-823.16,1596 v1@-800,1531 ; v1@-821,1525.4 R6.2@-809.23,1591.14 ; v1@-820.74,1521.71 R6.2@-820.91,1589.68 ; v1@-820.74,1528.32 R6.2@-800,1591.5 ; v1@-820.08,1531.14 R6.2@-790.77,1591.14 ; v1@-818.74,1534.47 R6.2@-779.09,1589.68 ; R6.2@-810.47,1599.2 v1@-800,1531 ; v1@-807.98,1524.37 R6.2@-809.23,1591.14 ; v1@-807.99,1525.48 R6.2@-800,1591.5 ; v1@-807.84,1526.58 R6.2@-790.77,1591.14 ; v1@-807.74,1522.99 R6.2@-820.91,1589.68 ; v1@-807.45,1527.9 R6.2@-779.09,1589.68 ; v1@-805.97,1530.33 -850,1475 ; R6.2 v1(-800,1525) ; v1@-794.67,1519.03 -850,1475 ; v1@-792.55,1527.9 R6.2@-820.91,1589.68 ; v1@-792.26,1522.99 R6.2@-779.09,1589.68 ; v1@-792.16,1526.58 R6.2@-809.23,1591.14 ; v1@-792.02,1524.37 R6.2@-790.77,1591.14 ; v1@-792.01,1525.48 R6.2@-800,1591.5 ; R6.2@-789.53,1599.2 v1@-800,1531 ; v1@-781.26,1534.47 R6.2@-820.91,1589.68 ; v1@-779.92,1531.14 R6.2@-809.23,1591.14 ; v1@-779.26,1521.71 R6.2@-779.09,1589.68 ; v1@-779.26,1528.32 R6.2@-800,1591.5 ; v1@-779,1525.4 R6.2@-790.77,1591.14 ; R6.2@-776.84,1596 v1@-800,1531 ; -850,1475 v1(-800,1525) ; -850,1475 v1(-800,1525) ; R6.2@-820.91,1589.68 v1(-800,1525) ; R6.2@-809.23,1591.14 v1(-800,1525) ; v1(-800,1525) R6.2@-790.77,1591.14 ; v1(-800,1525) R6.2@-779.09,1589.68
  Bottom w25: R6.2 C4.2
X00035: C5.2 R10.2 U1.20 U4.3 | length 1510.1
  Bottom w12: U4.3@-1230.03,1429.43 -1172.96,1382.96 ; U4.3 -1110,1320 -1110,1319
  Bottom w13: -1110,1319 -896,1319 -875,1340 U1.20 -875,1500 ; -875,1363.5 U1.20@-875,1409 ; U1.20@-875,1461 -875,1500 ; R10.2@-819.15,1713.62 -850,1650 ; R10.2@-807.96,1706.85 -850,1650 ; R10.2@-793.15,1692.04 -850,1650 ; R10.2@-786.38,1680.85 -850,1650 ; -875,1500 -850,1525 -850,1650 ; -850,1650 R10.2 -850,1650
  Bottom w30: R10.2 C5.2 R10.2
pads on no net: J1.3 U1.5 U1.6 U1.10 U3.6
copper on no net: | length 18
  Top w10: -536.9,1646 -524.2,1633.3

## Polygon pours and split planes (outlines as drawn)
GND on Bottom "Bottom-GND_F" (solid, remove dead copper, pour order 6): -3,1904 -267,1903 -267,1508 -371,1508 -369,778 -1742,778 -1742,4 -1739,1 -1074,2 -4,1 -4,589 38,589 38,887 -84,887 -84,1015 37,1015 37,1308 -3,1308
GND on Bottom "Bottom-GND" (solid, remove dead copper, pour order 4): -2425.43,863.03 -2464.43,863.03 -2464.43,374.03 -2372.43,374.03 -2093.43,7.03 -2093.43,6.03 -1861.43,6.03 -1861.43,814.03 -547.43,814.03 -547.43,1618.03 -371.43,1618.03 -371.43,1907.03 -2092.43,1909.03 -2378.43,1551.03 -2464.43,1551.03 -2464.43,1063.03 -2425.43,1063.03
GND on Top "Top-No Net" (solid, pour order 4): -2380,1530 -2365,1545 -2295,1545 -2295,1560 -2162.08,1692.92 -2162.08,1747.92 -2005,1905 -0.08,1905 -0.08,1325.08 10,1315 45,1315 45,1045 15,1015 -70,1015 -70,900 -80,890 40,890 40,590 0,590 0,0 -2005,0 -2005,15 -2143.08,180 -2200.62,255 -2260,330 -2275,351.96 -2300,365 -2385,350 -2377.95,365 -2377.95,810 -2385,835 -2365,855 -2345,855 -2345,1055 -2360,1070 -2377.95,1070 -2377.95,1490 -2375,1520 -2377.95,1522.95 -2377.95,1527.95

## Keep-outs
Keep-Out Layer:
  lines w10: -2377.95,365 -2377.95,855 -2338.58,855 -2338.58,1055 -2377.95,1055 -2377.95,1545 -2295,1545 -2005,1905 -0.08,1905 0,1895 0,1310 40,1310 40,1015 -80,1015 -80,890 40,890 40,590 0,590 0,0 -2005,0 -2285,365 -2377.95,365 ; -1635,885 -1635,1010 -1440,1010 -1440,885 -1635,885

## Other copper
Multi-Layer:
  circle w5: c-2379.98,859.12 r2.5
  circle w5: c-2340.17,957.5 r2.5
  circle w5: c-2340.17,1058.25 r2.5
  circle w5: c-1972.22,9.08 r2.5
  circle w5: c-2379.98,857.98 r2.5
  circle w5: c-1972.22,9 r2.5
  circle w5: c-2340.17,958.72 r2.5
  circle w5: c-1972.22,9 r2.5
  circle w5: c-2340.61,1058.25 r2.5
  circle w5: c-2340.17,857.98 r2.5
  circle w5: c-2340.61,857.98 r2.5
  lines w1: -2380,1480 -2379.97,1480 ; -2380,1530 -2380,2325 ; -2377.95,1595 -2377.95,2085 ; -272.48,0 -272.45,0 ; -262.48,1900 -262.45,1900 ; -222.48,0 312.52,0 ; -212.48,1900 312.52,1900 ; 0,1405 0.03,1405 ; 0,1455 0,2085 ; 0,1835 0.03,1835 ; 0,1885 0,2325 ; -2377.95,1545 -2377.93,1545
  lines w10: -1396.14,2275 -2380,2275 ; -983.86,2275 0,2275 ; 262.52,882.5 262.52,0 ; 262.52,1017.5 262.52,1900 ; -2380,2275 -2280,2250 -2280,2300 -2380,2275 ; 0,2275 -100,2300 -100,2250 0,2275 ; 262.52,0 287.52,100 237.52,100 262.52,0 ; 262.52,1900 237.52,1800 287.52,1800 262.52,1900 ; -2710,900 -2710,1025 -2515,1025 -2515,900 -2710,900
  text "60.5Metr" at -1366.14,2237.5 h50
  text "48.3Metr" at 85.25,912.5 h50

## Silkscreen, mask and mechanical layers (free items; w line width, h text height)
Silkscreen Top:
  lines w10: -745.6,1646 -536.9,1646
Silkscreen Bottom:
  text "HT45F23A" at -993.6,1119.2 h40
  text "HT82V739" at -432.3,634.2 h40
